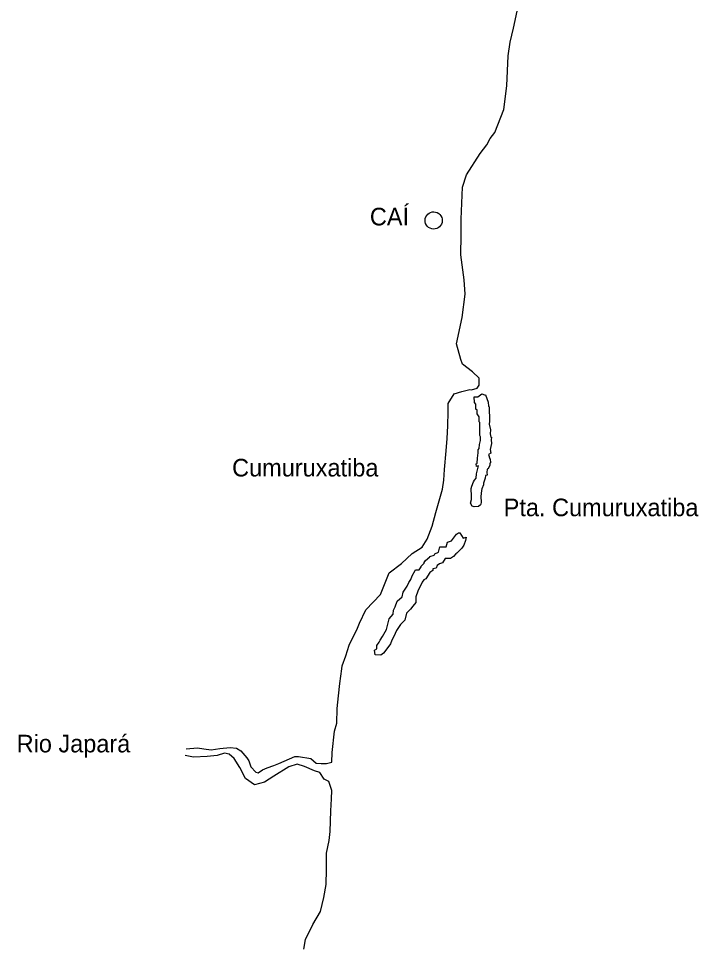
# Model space of a CAD drawing. Extents: x 662444 to 1640468, y 7452018 to 9606170.
# Drawn here: x 1104564 to 1129936, y 8083187 to 8117861 of the extents above; entities that cross this region are included whole.
import ezdxf

# ---------------------------------------------------------------- set-up
doc = ezdxf.new("R2010")
doc.units = 0
for name, color, linetype in [('Level 1', 7, 'Continuous'), ('Level 2', 7, 'Continuous'), ('Level 3', 7, 'Continuous')]:
    doc.layers.add(name, color=color, linetype=linetype)

msp = doc.modelspace()

# ---------------------------------------------------------------- linework, layer by layer
at = {"layer": 'Level 1'}
for points in [[(1121066, 8105143), (1120908, 8105728), (1121124, 8106720), (1121225, 8107584), (1121198, 8108119), (1121065, 8109057), (1121087, 8109779), (1121084, 8110380), (1121130, 8111579), (1121283, 8112031), (1121788, 8112828), (1122044, 8113154), (1122169, 8113394), (1122336, 8113612), (1122672, 8114469), (1122784, 8115356), (1122839, 8116477), (1122907, 8116976), (1123030, 8117506), (1123177, 8118135)], [(1115675, 8090093), (1115861, 8090086), (1116054, 8090080), (1116258, 8090136), (1116269, 8090491), (1116356, 8091284), (1116443, 8091591), (1116459, 8092132), (1116497, 8092610), (1116550, 8093064), (1116628, 8093610), (1116639, 8093727), (1116776, 8094101), (1116896, 8094492), (1117211, 8095131), (1117293, 8095314), (1117518, 8095809), (1118071, 8096379), (1118398, 8097189), (1118851, 8097538), (1119258, 8097912), (1119622, 8098148), (1119810, 8098443), (1119995, 8098933), (1120136, 8099446), (1120380, 8100311), (1120429, 8100650), (1120464, 8101044), (1120525, 8101745), (1120562, 8102207), (1120585, 8102678), (1120593, 8103196), (1120602, 8103505), (1120815, 8103862), (1121104, 8103954), (1121409, 8104029), (1121471, 8104019), (1121682, 8104074), (1121756, 8104188), (1121757, 8104451), (1121500, 8104691), (1121136, 8104980), (1121066, 8105143)], [(1121562, 8099649), (1121492, 8099674), (1121426, 8099792), (1121469, 8099929), (1121469, 8100170), (1121455, 8100201), (1121459, 8100340), (1121485, 8100424), (1121545, 8100592), (1121577, 8100646), (1121642, 8100728), (1121654, 8100882), (1121733, 8101181), (1121655, 8101160), (1121635, 8101262), (1121682, 8101276), (1121688, 8101469), (1121710, 8101669), (1121713, 8101785), (1121753, 8101823), (1121766, 8101977), (1121802, 8102130), (1121805, 8102261), (1121776, 8102317), (1121779, 8102409), (1121778, 8102618), (1121783, 8102804), (1121753, 8102828), (1121759, 8103013), (1121676, 8103116), (1121680, 8103255), (1121628, 8103295), (1121633, 8103481), (1121573, 8103545), (1121564, 8103761), (1121626, 8103759), (1121704, 8103757), (1121855, 8103868), (1121954, 8103826), (1121985, 8103825), (1122094, 8103559), (1122104, 8103404), (1122120, 8103388), (1122129, 8103202), (1122140, 8103032), (1122142, 8102846), (1122130, 8102739), (1122171, 8102521), (1122166, 8102374), (1122193, 8102250), (1122208, 8102249), (1122206, 8102156), (1122216, 8102017), (1122164, 8101795), (1122190, 8101655), (1122096, 8101603), (1122152, 8101447), (1122168, 8101439), (1122178, 8101291), (1122147, 8101277), (1122145, 8101199), (1122078, 8101054), (1122047, 8101056), (1122044, 8100932), (1122048, 8100832), (1121986, 8100818), (1121983, 8100718), (1121915, 8100542), (1121913, 8100472), (1121847, 8100327), (1121836, 8100266), (1121815, 8100035), (1121823, 8099833), (1121821, 8099749), (1121805, 8099726), (1121725, 8099667), (1121562, 8099649)], [(1121263, 8098521), (1121245, 8098398), (1121185, 8098230), (1121111, 8098116), (1120919, 8097930), (1120888, 8097907), (1120799, 8097802), (1120680, 8097728), (1120479, 8097726), (1120388, 8097560), (1120271, 8097532), (1120191, 8097472), (1120142, 8097366), (1120025, 8097346), (1120023, 8097285), (1119911, 8097203), (1119764, 8096968), (1119694, 8096931), (1119629, 8096841), (1119463, 8096506), (1119394, 8096292), (1119388, 8096091), (1119275, 8095947), (1119195, 8095842), (1119035, 8095692), (1118973, 8095432), (1118820, 8095266), (1118674, 8095039), (1118574, 8094817), (1118492, 8094681), (1118441, 8094543), (1118303, 8094354), (1118182, 8094196), (1118079, 8094122), (1117870, 8094136), (1117844, 8094307), (1117932, 8094359), (1117932, 8094374), (1117935, 8094482), (1118025, 8094610), (1118058, 8094687), (1118148, 8094824), (1118294, 8095082), (1118400, 8095480), (1118545, 8095646), (1118550, 8095800), (1118623, 8095929), (1118692, 8096136), (1118875, 8096293), (1118920, 8096468), (1119065, 8096696), (1119132, 8096834), (1119198, 8096939), (1119248, 8097077), (1119370, 8097275), (1119379, 8097305), (1119519, 8097300), (1119592, 8097415), (1119593, 8097445), (1119705, 8097550), (1119706, 8097580), (1119755, 8097657), (1119906, 8097783), (1119914, 8097799), (1120071, 8097855), (1120104, 8097901), (1120230, 8097966), (1120290, 8098165), (1120523, 8098158), (1120575, 8098335), (1120723, 8098384), (1120790, 8098490), (1120909, 8098633), (1120982, 8098685), (1121027, 8098684), (1121154, 8098486), (1121263, 8098521)], [(1110822, 8090630), (1111242, 8090663), (1111473, 8090633), (1111751, 8090593), (1112078, 8090645), (1112460, 8090679), (1112699, 8090656), (1112852, 8090559), (1113076, 8090297), (1113158, 8090186), (1113228, 8089952), (1113424, 8089761), (1113509, 8089735), (1113667, 8089846), (1113839, 8089925), (1114091, 8090002), (1114272, 8090082), (1114876, 8090349), (1115009, 8090345), (1115471, 8090269), (1115675, 8090093)], [(1115604, 8089808), (1115229, 8089967), (1114960, 8090061), (1114655, 8089954), (1114094, 8089608), (1113745, 8089388), (1113363, 8089283), (1113036, 8089518), (1112824, 8089927), (1112610, 8090273), (1112421, 8090426), (1112251, 8090462), (1111977, 8090378), (1111596, 8090343), (1111092, 8090319), (1110784, 8090383)], [(1115206, 8083157), (1115271, 8083519), (1115544, 8084074), (1115830, 8084568), (1115955, 8085081), (1116040, 8085566), (1116045, 8085752), (1116051, 8085937), (1116052, 8086733), (1116161, 8087209), (1116195, 8087548), (1116217, 8088313), (1116239, 8088760), (1116249, 8089077), (1116142, 8089405), (1115967, 8089503), (1115812, 8089748), (1115604, 8089808)]]:
    msp.add_lwpolyline(points, dxfattribs=at)
at = {"layer": 'Level 2'}
msp.add_ellipse((1120055, 8110333), major_axis=(321, -10), ratio=0.999997, dxfattribs=at)

# ---------------------------------------------------------------- texts
at = {"layer": 'Level 3'}
for s, height, p in [('CAÍ', 656.4, (1117674, 8110148)), ('Cumuruxatiba', 656.11, (1112532, 8100786)), ('Pta. Cumuruxatiba', 656.18, (1122669, 8099304)), ('Rio Japará', 655.7, (1104492, 8090496))]:
    msp.add_text(s, height=height, dxfattribs=at).set_placement(p)

doc.saveas('drawing.dxf')
